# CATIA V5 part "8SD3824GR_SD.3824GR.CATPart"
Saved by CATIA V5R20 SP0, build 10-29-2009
Part number: 8SD3824GR_SD.3824GR
Revision: ANY
Definition: UNKNOWN
Nomenclature: 8SD3824GR_SD.3824GR
Source: Unknown
Bounding box of the stored display mesh (mm): x -19 to 19, y -20 to 20, z -12 to 12
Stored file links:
  C:\Users\Utente\Desktop\IO LAVORO\3D X SITO CF\CUMSA\3D files SD\SD 3824\8SD3824GR_SD.3824GR.CATPart
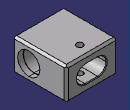
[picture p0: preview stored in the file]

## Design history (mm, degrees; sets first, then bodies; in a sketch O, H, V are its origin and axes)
Body1 "Chaflán3" (main body)
  Solid1: solid without history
